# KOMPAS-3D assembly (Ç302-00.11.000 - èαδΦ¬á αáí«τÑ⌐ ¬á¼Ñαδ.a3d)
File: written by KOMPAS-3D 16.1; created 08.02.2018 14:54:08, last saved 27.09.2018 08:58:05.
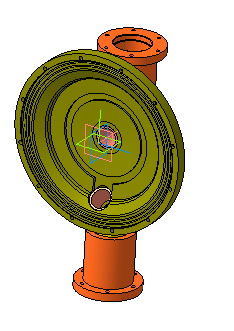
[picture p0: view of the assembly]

Referenced files in Z:\Мембранные насосы\Мембранный электропривод\А302-00.00.000 - ASTRA-302 (МЭ200)\3Д\: А302-00.12.000 - Крышка.a3d, А302-00.11.001 - Колена 45гр ф40.m3d, А302-00.31.000 - Корпус.a3d
Referenced files in Z:\1 ПКИ 3D\Полипропиленовые фитинги, трубы\: Колено 90гр 40 FV PPR ф. FV PLAST.m3d
Referenced files in Z:\Мембранные насосы\Мембранный электропривод\А302-00.00.000 - ASTRA-302 (МЭ200)\Чертежи\: А302-00.12.000 - Крышка.cdw, А302-00.11.001 - Колено 45гр ф40.cdw, А302-00.31.000 - Корпус.cdw
Referenced files: graphic.tdp
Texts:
  Колено 45гр ф40
  Колено 90@1~ @2~40 FV PPR ф. "FV PLAST"
  Крышка рабочей камеры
